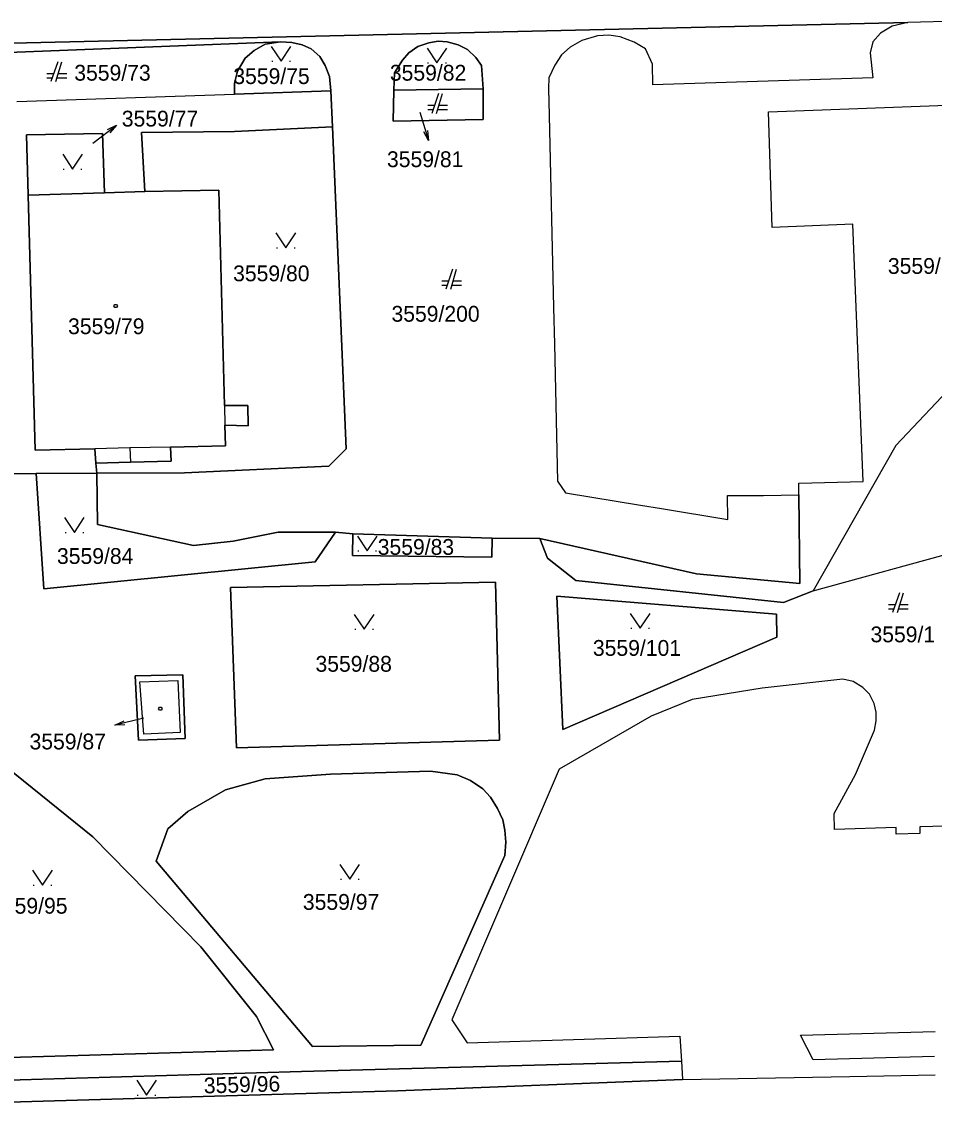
# Model space of a CAD drawing. Extents: x -263587 to -261993, y -1238795 to -1236748.
# Drawn here: x -262864 to -262771.6, y -1238356.5 to -1238246.6 of the extents above; entities that cross this region are included whole.
import ezdxf

# ---------------------------------------------------------------- set-up
doc = ezdxf.new("R2010")
doc.units = 0
doc.layers.add('Vrstva 1', color=7, linetype='Continuous')

msp = doc.modelspace()

# ---------------------------------------------------------------- linework, layer by layer
at = {"layer": 'Vrstva 1'}
for p, q in [((-262751.84, -1238246.22), (-262774.26, -1238246.7)), ((-262886.4, -1238249.29), (-262774.26, -1238246.7)), ((-262774.26, -1238246.7), (-262886.4, -1238249.29)), ((-262775.82, -1238247.1), (-262777.01, -1238247.81)), ((-262774.26, -1238246.7), (-262775.82, -1238247.1)), ((-262821.81, -1238248.6), (-262822.75, -1238248.77)), ((-262822.75, -1238248.77), (-262821.81, -1238248.6)), ((-262820.87, -1238248.66), (-262821.81, -1238248.6)), ((-262821.81, -1238248.6), (-262820.87, -1238248.66)), ((-262807.27, -1238248.55), (-262808.44, -1238249.21)), ((-262805.67, -1238248.06), (-262807.27, -1238248.55)), ((-262804.53, -1238248), (-262805.67, -1238248.06)), ((-262803.38, -1238248.18), (-262804.53, -1238248)), ((-262801.95, -1238248.69), (-262803.38, -1238248.18)), ((-262777.01, -1238247.81), (-262777.78, -1238248.67)), ((-262837.76, -1238248.66), (-262866.2, -1238249.79)), ((-262866.2, -1238249.79), (-262837.76, -1238248.66)), ((-262841.34, -1238250.32), (-262840.42, -1238249.54)), ((-262840.42, -1238249.54), (-262841.34, -1238250.32)), ((-262840.42, -1238249.54), (-262839.3, -1238248.91)), ((-262839.3, -1238248.91), (-262840.42, -1238249.54)), ((-262839.3, -1238248.91), (-262837.76, -1238248.66)), ((-262837.76, -1238248.66), (-262839.3, -1238248.91)), ((-262836.61, -1238248.74), (-262837.76, -1238248.66)), ((-262837.76, -1238248.66), (-262836.61, -1238248.74)), ((-262835.55, -1238248.96), (-262836.61, -1238248.74)), ((-262836.61, -1238248.74), (-262835.55, -1238248.96)), ((-262834.67, -1238249.37), (-262835.55, -1238248.96)), ((-262835.55, -1238248.96), (-262834.67, -1238249.37)), ((-262833.77, -1238250.15), (-262834.67, -1238249.37)), ((-262834.67, -1238249.37), (-262833.77, -1238250.15)), ((-262823.84, -1238249.16), (-262824.76, -1238249.77)), ((-262824.76, -1238249.77), (-262823.84, -1238249.16)), ((-262822.75, -1238248.77), (-262823.84, -1238249.16)), ((-262823.84, -1238249.16), (-262822.75, -1238248.77)), ((-262819.78, -1238248.97), (-262820.87, -1238248.66)), ((-262820.87, -1238248.66), (-262819.78, -1238248.97)), ((-262818.84, -1238249.46), (-262819.78, -1238248.97)), ((-262819.78, -1238248.97), (-262818.84, -1238249.46)), ((-262817.98, -1238250.24), (-262818.84, -1238249.46)), ((-262818.84, -1238249.46), (-262817.98, -1238250.24)), ((-262808.44, -1238249.21), (-262809.3, -1238249.99)), ((-262800.82, -1238249.39), (-262801.95, -1238248.69)), ((-262800.1, -1238250.94), (-262800.82, -1238249.39)), ((-262777.78, -1238248.67), (-262778.05, -1238249.78)), ((-262860.3, -1238250.7), (-262861, -1238252.7)), ((-262860.5, -1238252.7), (-262859.9, -1238250.7)), ((-262842.12, -1238251.63), (-262841.34, -1238250.32)), ((-262841.34, -1238250.32), (-262842.12, -1238251.63)), ((-262838.65, -1238250.64), (-262838.55, -1238250.64)), ((-262836.85, -1238250.64), (-262836.75, -1238250.64)), ((-262833.23, -1238251.07), (-262833.77, -1238250.15)), ((-262833.77, -1238250.15), (-262833.23, -1238251.07)), ((-262825.41, -1238250.53), (-262826.21, -1238251.8)), ((-262826.21, -1238251.8), (-262825.41, -1238250.53)), ((-262824.76, -1238249.77), (-262825.41, -1238250.53)), ((-262825.41, -1238250.53), (-262824.76, -1238249.77)), ((-262822.87, -1238250.81), (-262822.77, -1238250.81)), ((-262821.07, -1238250.81), (-262820.97, -1238250.81)), ((-262817.4, -1238251.08), (-262817.98, -1238250.24)), ((-262817.98, -1238250.24), (-262817.4, -1238251.08)), ((-262809.3, -1238249.99), (-262809.99, -1238251.03)), ((-262778.05, -1238249.78), (-262777.8, -1238252.3)), ((-262860.72, -1238251.9), (-262861.4, -1238251.9)), ((-262859.4, -1238251.9), (-262860.26, -1238251.9)), ((-262842.41, -1238252.84), (-262842.12, -1238251.63)), ((-262842.12, -1238251.63), (-262842.41, -1238252.84)), ((-262832.8, -1238252.18), (-262833.23, -1238251.07)), ((-262833.23, -1238251.07), (-262832.8, -1238252.18)), ((-262826.21, -1238251.8), (-262826.29, -1238253.56)), ((-262826.29, -1238253.56), (-262826.21, -1238251.8)), ((-262817.24, -1238253.43), (-262817.4, -1238251.08)), ((-262817.4, -1238251.08), (-262817.24, -1238253.43)), ((-262809.99, -1238251.03), (-262810.6, -1238252.3)), ((-262800.06, -1238253.03), (-262800.1, -1238250.94)), ((-262861.4, -1238252.3), (-262860.86, -1238252.3)), ((-262860.38, -1238252.3), (-262859.4, -1238252.3)), ((-262842.4, -1238253.97), (-262842.41, -1238252.84)), ((-262842.41, -1238252.84), (-262842.4, -1238253.97)), ((-262832.68, -1238253.63), (-262832.8, -1238252.18)), ((-262832.8, -1238252.18), (-262832.68, -1238253.63)), ((-262810.6, -1238252.3), (-262810.62, -1238253.38)), ((-262777.8, -1238252.3), (-262800.06, -1238253.03)), ((-262864.46, -1238254.71), (-262842.4, -1238253.97)), ((-262832.68, -1238253.63), (-262842.4, -1238253.97)), ((-262842.4, -1238253.97), (-262832.68, -1238253.63)), ((-262832.51, -1238257.28), (-262832.68, -1238253.63)), ((-262832.68, -1238253.63), (-262832.51, -1238257.28)), ((-262826.29, -1238253.56), (-262826.37, -1238256.7)), ((-262826.37, -1238256.7), (-262826.29, -1238253.56)), ((-262817.24, -1238253.43), (-262826.29, -1238253.56)), ((-262826.29, -1238253.56), (-262817.24, -1238253.43)), ((-262821.75, -1238253.91), (-262822.45, -1238255.91)), ((-262821.95, -1238255.91), (-262821.35, -1238253.91)), ((-262817.24, -1238256.52), (-262817.24, -1238253.43)), ((-262817.24, -1238253.43), (-262817.24, -1238256.52)), ((-262810.62, -1238253.38), (-262810.56, -1238256.11)), ((-262822.17, -1238255.11), (-262822.85, -1238255.11)), ((-262820.85, -1238255.11), (-262821.71, -1238255.11)), ((-262788.36, -1238255.76), (-262769.38, -1238255.06)), ((-262822.85, -1238255.51), (-262822.31, -1238255.51)), ((-262821.83, -1238255.51), (-262820.85, -1238255.51)), ((-262810.56, -1238256.11), (-262810.11, -1238275.55)), ((-262787.98, -1238267.45), (-262788.36, -1238255.76)), ((-262855.29, -1238257.55), (-262854.37, -1238257.11)), ((-262842.4, -1238257.74), (-262832.51, -1238257.28)), ((-262832.51, -1238257.28), (-262842.4, -1238257.74)), ((-262831.11, -1238289.87), (-262832.51, -1238257.28)), ((-262832.51, -1238257.28), (-262831.11, -1238289.87)), ((-262826.37, -1238256.7), (-262817.24, -1238256.52)), ((-262817.24, -1238256.52), (-262826.37, -1238256.7)), ((-262863.49, -1238258.09), (-262855.79, -1238257.94)), ((-262855.79, -1238257.94), (-262863.49, -1238258.09)), ((-262863.32, -1238264.19), (-262863.49, -1238258.09)), ((-262863.49, -1238258.09), (-262863.32, -1238264.19)), ((-262855.79, -1238257.94), (-262855.58, -1238263.94)), ((-262855.58, -1238263.94), (-262855.79, -1238257.94)), ((-262851.82, -1238257.85), (-262842.4, -1238257.74)), ((-262842.4, -1238257.74), (-262851.82, -1238257.85)), ((-262851.51, -1238263.81), (-262851.82, -1238257.85)), ((-262851.82, -1238257.85), (-262851.51, -1238263.81)), ((-262822.878, -1238257.646), (-262822.779, -1238258.661)), ((-262859.76, -1238261.55), (-262859.66, -1238261.55)), ((-262857.96, -1238261.55), (-262857.86, -1238261.55)), ((-262863.32, -1238264.19), (-262855.58, -1238263.94)), ((-262855.58, -1238263.94), (-262863.32, -1238264.19)), ((-262855.58, -1238263.94), (-262851.51, -1238263.81)), ((-262851.51, -1238263.81), (-262855.58, -1238263.94)), ((-262843.99, -1238263.68), (-262851.51, -1238263.81)), ((-262851.51, -1238263.81), (-262843.99, -1238263.68)), ((-262843.43, -1238285.46), (-262843.99, -1238263.68)), ((-262843.99, -1238263.68), (-262843.43, -1238285.46)), ((-262862.6, -1238289.99), (-262863.32, -1238264.19)), ((-262863.32, -1238264.19), (-262862.6, -1238289.99)), ((-262779.83, -1238267.11), (-262787.98, -1238267.45)), ((-262778.76, -1238293.16), (-262779.83, -1238267.11)), ((-262838.17, -1238269.51), (-262838.07, -1238269.51)), ((-262836.37, -1238269.51), (-262836.27, -1238269.51)), ((-262820.33, -1238271.69), (-262821.03, -1238273.69)), ((-262820.53, -1238273.69), (-262819.93, -1238271.69)), ((-262757.84, -1238270.76), (-262775.45, -1238289.53)), ((-262820.75, -1238272.89), (-262821.43, -1238272.89)), ((-262821.43, -1238273.29), (-262820.89, -1238273.29)), ((-262820.41, -1238273.29), (-262819.43, -1238273.29)), ((-262819.43, -1238272.89), (-262820.29, -1238272.89)), ((-262810.11, -1238275.55), (-262810.02, -1238279.27)), ((-262810.02, -1238279.27), (-262809.7, -1238293.11)), ((-262841.05, -1238285.48), (-262843.43, -1238285.46)), ((-262843.43, -1238285.46), (-262841.05, -1238285.48)), ((-262843.43, -1238285.46), (-262843.38, -1238287.47)), ((-262841.03, -1238287.51), (-262841.05, -1238285.48)), ((-262841.05, -1238285.48), (-262841.03, -1238287.51)), ((-262843.33, -1238289.54), (-262843.38, -1238287.47)), ((-262843.38, -1238287.47), (-262841.03, -1238287.51)), ((-262841.03, -1238287.51), (-262843.38, -1238287.47)), ((-262843.38, -1238287.47), (-262843.33, -1238289.54)), ((-262856.56, -1238289.85), (-262862.6, -1238289.99)), ((-262862.6, -1238289.99), (-262856.56, -1238289.85)), ((-262853.01, -1238289.76), (-262856.56, -1238289.85)), ((-262856.45, -1238291.29), (-262856.56, -1238289.85)), ((-262856.56, -1238289.85), (-262856.45, -1238291.29)), ((-262848.91, -1238289.67), (-262853.01, -1238289.76)), ((-262853.01, -1238289.76), (-262852.95, -1238291.21)), ((-262848.91, -1238289.67), (-262843.33, -1238289.54)), ((-262843.33, -1238289.54), (-262848.91, -1238289.67)), ((-262848.83, -1238291.1), (-262848.91, -1238289.67)), ((-262848.91, -1238289.67), (-262848.83, -1238291.1)), ((-262832.86, -1238291.6), (-262831.11, -1238289.87)), ((-262831.11, -1238289.87), (-262832.86, -1238291.6)), ((-262775.45, -1238289.53), (-262783.83, -1238304.22)), ((-262856.45, -1238291.29), (-262852.95, -1238291.21)), ((-262852.95, -1238291.21), (-262856.45, -1238291.29)), ((-262856.37, -1238292.3), (-262856.45, -1238291.29)), ((-262856.45, -1238291.29), (-262856.37, -1238292.3)), ((-262852.95, -1238291.21), (-262848.83, -1238291.1)), ((-262848.83, -1238291.1), (-262852.95, -1238291.21)), ((-262862.5, -1238292.36), (-262865.03, -1238292.39)), ((-262865.03, -1238292.39), (-262862.5, -1238292.36)), ((-262862.5, -1238292.36), (-262856.37, -1238292.3)), ((-262856.37, -1238292.3), (-262862.5, -1238292.36)), ((-262861.73, -1238304.03), (-262862.5, -1238292.36)), ((-262862.5, -1238292.36), (-262861.73, -1238304.03)), ((-262856.37, -1238292.3), (-262847.49, -1238292.27)), ((-262847.49, -1238292.27), (-262856.37, -1238292.3)), ((-262856.29, -1238297.5), (-262856.37, -1238292.3)), ((-262856.37, -1238292.3), (-262856.29, -1238297.5)), ((-262847.49, -1238292.27), (-262832.86, -1238291.6)), ((-262832.86, -1238291.6), (-262847.49, -1238292.27)), ((-262809.7, -1238293.11), (-262808.92, -1238294.3)), ((-262785.29, -1238293.34), (-262778.76, -1238293.16)), ((-262785.27, -1238294.52), (-262785.29, -1238293.34)), ((-262808.92, -1238294.3), (-262801.33, -1238295.54)), ((-262792.5, -1238294.59), (-262788.85, -1238294.56)), ((-262792.46, -1238297.02), (-262792.5, -1238294.59)), ((-262788.85, -1238294.56), (-262785.27, -1238294.52)), ((-262785.27, -1238294.52), (-262785.18, -1238303.47)), ((-262785.18, -1238303.47), (-262785.27, -1238294.52)), ((-262801.33, -1238295.54), (-262799.2, -1238295.9)), ((-262799.2, -1238295.9), (-262792.46, -1238297.02)), ((-262846.56, -1238299.64), (-262856.29, -1238297.5)), ((-262856.29, -1238297.5), (-262846.56, -1238299.64)), ((-262859.57, -1238298.31), (-262859.47, -1238298.31)), ((-262857.77, -1238298.31), (-262857.67, -1238298.31)), ((-262838, -1238298.3), (-262842.56, -1238299.18)), ((-262842.56, -1238299.18), (-262838, -1238298.3)), ((-262832.18, -1238298.29), (-262838, -1238298.3)), ((-262838, -1238298.3), (-262832.18, -1238298.29)), ((-262832.18, -1238298.29), (-262834.25, -1238301.3)), ((-262834.25, -1238301.3), (-262832.18, -1238298.29)), ((-262830.44, -1238298.45), (-262832.18, -1238298.29)), ((-262832.18, -1238298.29), (-262830.44, -1238298.45)), ((-262830.48, -1238300.64), (-262830.44, -1238298.45)), ((-262830.44, -1238298.45), (-262830.48, -1238300.64)), ((-262816.33, -1238298.89), (-262830.44, -1238298.45)), ((-262830.44, -1238298.45), (-262816.33, -1238298.89)), ((-262816.33, -1238298.89), (-262816.35, -1238300.81)), ((-262816.35, -1238300.81), (-262816.33, -1238298.89)), ((-262811.52, -1238298.91), (-262816.33, -1238298.89)), ((-262816.33, -1238298.89), (-262811.52, -1238298.91)), ((-262795.65, -1238302.49), (-262811.52, -1238298.91)), ((-262810.72, -1238300.91), (-262811.52, -1238298.91)), ((-262811.52, -1238298.91), (-262795.65, -1238302.49)), ((-262811.52, -1238298.91), (-262810.72, -1238300.91)), ((-262842.56, -1238299.18), (-262846.56, -1238299.64)), ((-262846.56, -1238299.64), (-262842.56, -1238299.18)), ((-262829.93, -1238300.18), (-262829.83, -1238300.18)), ((-262828.13, -1238300.18), (-262828.03, -1238300.18)), ((-262783.83, -1238304.22), (-262768.84, -1238300.11)), ((-262834.25, -1238301.3), (-262861.73, -1238304.03)), ((-262861.73, -1238304.03), (-262834.25, -1238301.3)), ((-262816.35, -1238300.81), (-262830.48, -1238300.64)), ((-262830.48, -1238300.64), (-262816.35, -1238300.81)), ((-262807.85, -1238303.16), (-262810.72, -1238300.91)), ((-262810.72, -1238300.91), (-262807.85, -1238303.16)), ((-262842.83, -1238303.88), (-262815.99, -1238303.34)), ((-262815.99, -1238303.34), (-262842.83, -1238303.88)), ((-262815.99, -1238303.34), (-262815.58, -1238319.33)), ((-262815.58, -1238319.33), (-262815.99, -1238303.34)), ((-262786.82, -1238305.39), (-262807.85, -1238303.16)), ((-262807.85, -1238303.16), (-262786.82, -1238305.39)), ((-262785.18, -1238303.47), (-262795.65, -1238302.49)), ((-262795.65, -1238302.49), (-262785.18, -1238303.47)), ((-262842.2, -1238320.12), (-262842.83, -1238303.88)), ((-262842.83, -1238303.88), (-262842.2, -1238320.12)), ((-262783.83, -1238304.22), (-262786.82, -1238305.39)), ((-262786.82, -1238305.39), (-262783.83, -1238304.22)), ((-262775.1, -1238304.43), (-262775.8, -1238306.43)), ((-262775.3, -1238306.43), (-262774.7, -1238304.43)), ((-262809.19, -1238318.24), (-262809.78, -1238304.77)), ((-262809.78, -1238304.77), (-262787.54, -1238306.57)), ((-262787.54, -1238306.57), (-262809.78, -1238304.77)), ((-262809.78, -1238304.77), (-262809.19, -1238318.24)), ((-262775.52, -1238305.63), (-262776.2, -1238305.63)), ((-262774.2, -1238305.63), (-262775.06, -1238305.63)), ((-262787.54, -1238306.57), (-262787.52, -1238308.92)), ((-262787.52, -1238308.92), (-262787.54, -1238306.57)), ((-262776.2, -1238306.03), (-262775.66, -1238306.03)), ((-262775.18, -1238306.03), (-262774.2, -1238306.03)), ((-262830.24, -1238308.11), (-262830.14, -1238308.11)), ((-262828.44, -1238308.11), (-262828.34, -1238308.11)), ((-262787.52, -1238308.92), (-262809.19, -1238318.24)), ((-262809.19, -1238318.24), (-262787.52, -1238308.92)), ((-262802.3, -1238308), (-262802.2, -1238308)), ((-262800.5, -1238308), (-262800.4, -1238308)), ((-262852.47, -1238312.82), (-262847.66, -1238312.72)), ((-262847.66, -1238312.72), (-262852.47, -1238312.82)), ((-262852.13, -1238319.34), (-262852.47, -1238312.82)), ((-262852.47, -1238312.82), (-262852.13, -1238319.34)), ((-262852, -1238313.44), (-262848.15, -1238313.29)), ((-262851.6, -1238318.74), (-262852, -1238313.44)), ((-262848.15, -1238313.29), (-262847.92, -1238318.57)), ((-262847.66, -1238312.72), (-262847.4, -1238319.15)), ((-262847.4, -1238319.15), (-262847.66, -1238312.72)), ((-262780.83, -1238313.15), (-262789, -1238314.06)), ((-262779.77, -1238313.38), (-262780.83, -1238313.15)), ((-262778.8, -1238313.99), (-262779.77, -1238313.38)), ((-262789, -1238314.06), (-262796.08, -1238315.22)), ((-262778.13, -1238314.67), (-262778.8, -1238313.99)), ((-262796.08, -1238315.22), (-262800.22, -1238316.92)), ((-262777.65, -1238315.61), (-262778.13, -1238314.67)), ((-262777.45, -1238316.49), (-262777.65, -1238315.61)), ((-262777.45, -1238317.39), (-262777.45, -1238316.49)), ((-262853.51, -1238317.765), (-262854.529, -1238317.8)), ((-262800.22, -1238316.92), (-262809.55, -1238322.28)), ((-262777.63, -1238318.31), (-262777.45, -1238317.39)), ((-262847.92, -1238318.57), (-262851.6, -1238318.74)), ((-262779.55, -1238322.8), (-262777.63, -1238318.31)), ((-262847.4, -1238319.15), (-262852.13, -1238319.34)), ((-262852.13, -1238319.34), (-262847.4, -1238319.15)), ((-262815.58, -1238319.33), (-262842.2, -1238320.12)), ((-262842.2, -1238320.12), (-262815.58, -1238319.33)), ((-262866.71, -1238321.11), (-262856.77, -1238329.11)), ((-262856.77, -1238329.11), (-262866.71, -1238321.11)), ((-262843.32, -1238324.36), (-262839.31, -1238323.23)), ((-262839.31, -1238323.23), (-262843.32, -1238324.36)), ((-262839.31, -1238323.23), (-262832.7, -1238322.78)), ((-262832.7, -1238322.78), (-262839.31, -1238323.23)), ((-262832.7, -1238322.78), (-262822.56, -1238322.48)), ((-262822.56, -1238322.48), (-262832.7, -1238322.78)), ((-262822.56, -1238322.48), (-262819.88, -1238322.83)), ((-262819.88, -1238322.83), (-262822.56, -1238322.48)), ((-262809.55, -1238322.28), (-262820.42, -1238347.62)), ((-262819.88, -1238322.83), (-262818.53, -1238323.42)), ((-262818.53, -1238323.42), (-262819.88, -1238322.83)), ((-262781.72, -1238326.75), (-262779.55, -1238322.8)), ((-262847.13, -1238326.54), (-262843.32, -1238324.36)), ((-262843.32, -1238324.36), (-262847.13, -1238326.54)), ((-262818.53, -1238323.42), (-262817.28, -1238324.26)), ((-262817.28, -1238324.26), (-262818.53, -1238323.42)), ((-262817.28, -1238324.26), (-262816.5, -1238325.09)), ((-262816.5, -1238325.09), (-262817.28, -1238324.26)), ((-262816.5, -1238325.09), (-262815.78, -1238326.24)), ((-262815.78, -1238326.24), (-262816.5, -1238325.09)), ((-262849.16, -1238328.3), (-262847.13, -1238326.54)), ((-262847.13, -1238326.54), (-262849.16, -1238328.3)), ((-262815.78, -1238326.24), (-262815.25, -1238327.41)), ((-262815.25, -1238327.41), (-262815.78, -1238326.24)), ((-262815.25, -1238327.41), (-262815.04, -1238328.43)), ((-262815.04, -1238328.43), (-262815.25, -1238327.41)), ((-262781.67, -1238328.36), (-262781.72, -1238326.75)), ((-262757.24, -1238327.64), (-262773.05, -1238328.11)), ((-262850.34, -1238331.56), (-262849.16, -1238328.3)), ((-262849.16, -1238328.3), (-262850.34, -1238331.56)), ((-262815.04, -1238328.43), (-262814.94, -1238329.64)), ((-262814.94, -1238329.64), (-262815.04, -1238328.43)), ((-262775.44, -1238328.18), (-262781.67, -1238328.36)), ((-262775.43, -1238328.83), (-262775.44, -1238328.18)), ((-262773.03, -1238328.76), (-262775.43, -1238328.83)), ((-262773.05, -1238328.11), (-262773.03, -1238328.76)), ((-262856.77, -1238329.11), (-262845.81, -1238340.26)), ((-262845.81, -1238340.26), (-262856.77, -1238329.11)), ((-262814.94, -1238329.64), (-262815.06, -1238330.99)), ((-262815.06, -1238330.99), (-262814.94, -1238329.64)), ((-262815.06, -1238330.99), (-262823.54, -1238350.21)), ((-262823.54, -1238350.21), (-262815.06, -1238330.99)), ((-262834.51, -1238350.32), (-262850.34, -1238331.56)), ((-262850.34, -1238331.56), (-262834.51, -1238350.32)), ((-262862.8, -1238334), (-262862.7, -1238334)), ((-262861, -1238334), (-262860.9, -1238334)), ((-262831.7, -1238333.4), (-262831.6, -1238333.4)), ((-262829.9, -1238333.4), (-262829.8, -1238333.4)), ((-262845.81, -1238340.26), (-262840.19, -1238347.28)), ((-262840.19, -1238347.28), (-262845.81, -1238340.26)), ((-262840.19, -1238347.28), (-262838.46, -1238350.65)), ((-262838.46, -1238350.65), (-262840.19, -1238347.28)), ((-262820.42, -1238347.62), (-262818.86, -1238349.97)), ((-262818.86, -1238349.97), (-262797.34, -1238349.27)), ((-262797.34, -1238349.27), (-262797.17, -1238351.81)), ((-262785.11, -1238349.17), (-262771.49, -1238348.82)), ((-262783.84, -1238351.68), (-262785.11, -1238349.17)), ((-262838.46, -1238350.65), (-262880.81, -1238351.92)), ((-262880.81, -1238351.92), (-262838.46, -1238350.65)), ((-262823.54, -1238350.21), (-262834.51, -1238350.32)), ((-262834.51, -1238350.32), (-262823.54, -1238350.21)), ((-262835.63, -1238352.85), (-262797.17, -1238351.81)), ((-262797.17, -1238351.81), (-262835.63, -1238352.85)), ((-262797.17, -1238351.81), (-262797.05, -1238353.67)), ((-262771.55, -1238351.33), (-262783.84, -1238351.68)), ((-262883.61, -1238354.27), (-262835.63, -1238352.85)), ((-262835.63, -1238352.85), (-262883.61, -1238354.27)), ((-262797.07, -1238353.67), (-262825.9, -1238354.8)), ((-262825.9, -1238354.8), (-262797.07, -1238353.67)), ((-262797.05, -1238353.67), (-262797.07, -1238353.67)), ((-262797.07, -1238353.67), (-262797.05, -1238353.67)), ((-262797.05, -1238353.67), (-262780.13, -1238353.36)), ((-262780.13, -1238353.36), (-262771.49, -1238353.2)), ((-262825.9, -1238354.8), (-262883.56, -1238356.48)), ((-262883.56, -1238356.48), (-262825.9, -1238354.8)), ((-262852.27, -1238355.24), (-262852.17, -1238355.24)), ((-262850.47, -1238355.24), (-262850.37, -1238355.24))]:
    msp.add_line(p, q, dxfattribs=at)
for points in [[(-262838.7, -1238249.14), (-262837.7, -1238250.64), (-262836.7, -1238249.14)], [(-262822.92, -1238249.31), (-262821.92, -1238250.81), (-262820.92, -1238249.31)], [(-262823.65, -1238255.79), (-262822.779, -1238258.661), (-262823.261, -1238257.762)], [(-262856.77, -1238258.91), (-262854.37, -1238257.11), (-262855.05, -1238257.87)], [(-262859.81, -1238260.05), (-262858.81, -1238261.55), (-262857.81, -1238260.05)], [(-262838.22, -1238268.01), (-262837.22, -1238269.51), (-262836.22, -1238268.01)], [(-262859.62, -1238296.81), (-262858.62, -1238298.31), (-262857.62, -1238296.81)], [(-262829.98, -1238298.68), (-262828.98, -1238300.18), (-262827.98, -1238298.68)], [(-262830.29, -1238306.61), (-262829.29, -1238308.11), (-262828.29, -1238306.61)], [(-262802.35, -1238306.5), (-262801.35, -1238308), (-262800.35, -1238306.5)], [(-262851.61, -1238317.11), (-262854.529, -1238317.8), (-262853.602, -1238317.376)], [(-262831.75, -1238331.9), (-262830.75, -1238333.4), (-262829.75, -1238331.9)], [(-262862.85, -1238332.5), (-262861.85, -1238334), (-262860.85, -1238332.5)], [(-262852.32, -1238353.74), (-262851.32, -1238355.24), (-262850.32, -1238353.74)]]:
    msp.add_lwpolyline(points, dxfattribs=at)
for points in [[(-262854.36, -1238275.25), (-262854.27, -1238275.4), (-262854.36, -1238275.55), (-262854.54, -1238275.55), (-262854.63, -1238275.4), (-262854.54, -1238275.25)], [(-262849.84, -1238316), (-262849.75, -1238316.15), (-262849.84, -1238316.3), (-262850.02, -1238316.3), (-262850.11, -1238316.15), (-262850.02, -1238316)]]:
    msp.add_lwpolyline(points, close=True, dxfattribs=at)

# ---------------------------------------------------------------- texts
for s, p in [('3559/73', (-262858.637, -1238252.6)), ('3559/75', (-262842.537, -1238252.94)), ('3559/82', (-262826.687, -1238252.6)), ('3559/77', (-262853.827, -1238257.24)), ('3559/81', (-262826.978, -1238261.35)), ('3559/109', (-262776.268, -1238272.15)), ('3559/80', (-262842.557, -1238272.9)), ('3559/200', (-262826.524, -1238276.99)), ('3559/79', (-262859.264, -1238278.25)), ('3559/83', (-262827.917, -1238300.58)), ('3559/84', (-262860.387, -1238301.5)), ('3559/1', (-262778.03, -1238309.43)), ('3559/101', (-262806.132, -1238310.8)), ('3559/88', (-262834.217, -1238312.41)), ('3559/87', (-262863.167, -1238320.27)), ('3559/95', (-262867.054, -1238336.89)), ('3559/97', (-262835.494, -1238336.5))]:
    msp.add_text(s, height=1.6, dxfattribs=at).set_placement(p)
msp.add_text('3559/96', height=1.6, rotation=1.54699, dxfattribs=at).set_placement((-262845.503, -1238355.081))

doc.saveas('drawing.dxf')
